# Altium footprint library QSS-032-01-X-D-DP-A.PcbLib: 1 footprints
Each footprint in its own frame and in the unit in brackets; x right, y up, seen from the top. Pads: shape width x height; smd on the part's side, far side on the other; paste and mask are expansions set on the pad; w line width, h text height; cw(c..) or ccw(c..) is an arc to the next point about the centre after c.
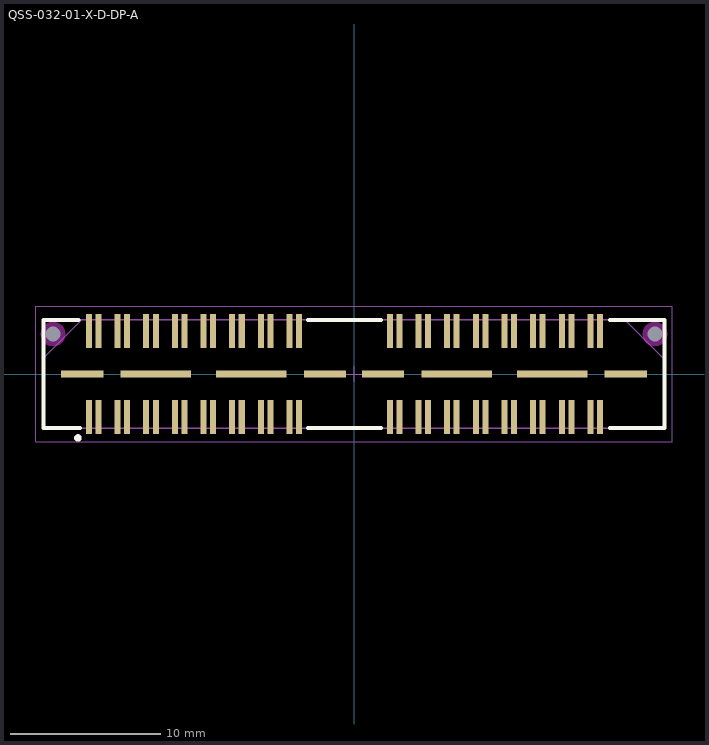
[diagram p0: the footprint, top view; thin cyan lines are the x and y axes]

## QSS-032-01-X-D-DP-A [mm] "0.635mm pitch, high speed socket; differential pair array"
height 3.43
pads (74):
  rect 0.4x2.25 smd mask+0: 1(-17.621,-2.865) 2(-17.621,2.865) 3(-16.986,-2.865) 4(-16.986,2.865) 5(-15.716,-2.865) 6(-15.716,2.865) 7(-15.081,-2.865) 8(-15.081,2.865) 9(-13.811,-2.865) 10(-13.811,2.865) 11(-13.176,-2.865) 12(-13.176,2.865) 13(-11.906,-2.865) 14(-11.906,2.865) 15(-11.271,-2.865) 16(-11.271,2.865) 17(-10.001,-2.865) 18(-10.001,2.865) 19(-9.366,-2.865) 20(-9.366,2.865) 21(-8.096,-2.865) 22(-8.096,2.865) 23(-7.461,-2.865) 24(-7.461,2.865) 25(-6.191,-2.865) 26(-6.191,2.865) 27(-5.556,-2.865) 28(-5.556,2.865) 29(-4.286,-2.865) 30(-4.286,2.865) 31(-3.651,-2.865) 32(-3.651,2.865) 33(2.381,-2.865) 34(2.381,2.865) 35(3.016,-2.865) 36(3.016,2.865) 37(4.286,-2.865) 38(4.286,2.865) 39(4.921,-2.865) 40(4.921,2.865) 41(6.191,-2.865) 42(6.191,2.865) 43(6.826,-2.865) 44(6.826,2.865) 45(8.096,-2.865) 46(8.096,2.865) 47(8.731,-2.865) 48(8.731,2.865) 49(10.001,-2.865) 50(10.001,2.865) 51(10.636,-2.865) 52(10.636,2.865) 53(11.906,-2.865) 54(11.906,2.865) 55(12.541,-2.865) 56(12.541,2.865) 57(13.811,-2.865) 58(13.811,2.865) 59(14.446,-2.865) 60(14.446,2.865) 61(15.716,-2.865) 62(15.716,2.865) 63(16.351,-2.865) 64(16.351,2.865)
  rect 2.8x0.45 smd mask+0: 65(-18.066,0) 68(-1.937,0) 69(1.937,0) 72(18.066,0)
  rect 4.7x0.45 smd mask+0: 66(-13.176,0) 67(-6.826,0) 70(6.826,0) 71(13.176,0)
  round 0.5 hole 1 unplated mask+0: 73(-20.004,2.657) 74(20.001,2.657)
Top Overlay:
  circle w0.25: c-18.35,-4.25 r0.125
  lines w0.254: -18.3,3.6 -20.65,3.6 -20.65,-3.6 -18.2,-3.6 ; -3.05,-3.6 1.815,-3.6 ; -3.05,3.6 1.815,3.6 ; 17,-3.6 20.65,-3.6 20.65,3.6 17,3.6
Keep-Out Layer:
  pour cut-out: -19.197,2.657 -19.225,2.866 -19.305,3.06 -19.433,3.228 -19.601,3.356 -19.795,3.436 -20.004,3.464 -20.213,3.436 -20.407,3.356 -20.575,3.228 -20.703,3.06 -20.783,2.866 -20.811,2.657 -20.783,2.448 -20.703,2.254 -20.575,2.086 -20.407,1.958 -20.213,1.878 -20.004,1.85 -19.795,1.878 -19.601,1.958 -19.433,2.086 -19.305,2.254 -19.225,2.448
  pour cut-out: 20.808,2.657 20.78,2.866 20.7,3.06 20.572,3.228 20.404,3.356 20.21,3.436 20.001,3.464 19.792,3.436 19.598,3.356 19.43,3.228 19.302,3.06 19.222,2.866 19.194,2.657 19.222,2.448 19.302,2.254 19.43,2.086 19.598,1.958 19.792,1.878 20.001,1.85 20.21,1.878 20.404,1.958 20.572,2.086 20.7,2.254 20.78,2.448
Mechanical 12:
  lines w0.001: -20.65,-3.6 20.65,-3.6 20.65,3.6 -20.65,3.6 -20.65,-3.6
Mechanical 13:
  lines w0.076: -20.65,1.05 -18.1,3.6 ; 18.005,3.605 20.655,0.955
  lines w0.1: -20.65,-3.6 20.65,-3.6 20.65,3.6 -20.65,3.6 -20.65,-3.6
  text ".Designator" at 0.254,0.254 h1.52
Mechanical 15:
  lines w0.05: -0.5,0 0.5,0 ; 0,-0.5 0,0.5 ; -21.15,-4.5 21.15,-4.5 21.15,4.5 -21.15,4.5 -21.15,-4.5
